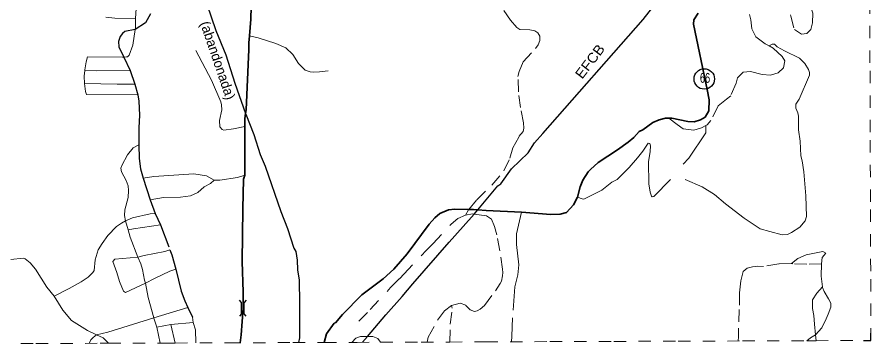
# Model space of a CAD drawing. Extents: x 423 to 448.8, y 7456.3 to 7484.
# Drawn here: x 441.81 to 448.76, y 7456.32 to 7458.99 of the extents above; entities that cross this region are included whole.
import ezdxf
from ezdxf.enums import TextEntityAlignment as Align

# ---------------------------------------------------------------- set-up
doc = ezdxf.new("R2010")
doc.units = 0
doc.header["$LTSCALE"] = 0.032
for name, pattern in [('LONG_DASHED', [7.5, 6, -1.5]), ('MEDIUM_DASHED', [4.5, 3, -1.5]), ('SHORT_DASHED', [2.7, 1.5, -1.2])]:
    doc.linetypes.add(name, pattern=pattern)
for name, color, linetype, lineweight in [('10', 7, 'Continuous', 25), ('13', 7, 'Continuous', 25), ('15', 7, 'Continuous', 25), ('2', 7, 'Continuous', 35), ('35', 7, 'SHORT_DASHED', 13), ('4', 7, 'LONG_DASHED', 25), ('5', 7, 'LONG_DASHED', 13), ('6', 7, 'MEDIUM_DASHED', 13), ('63', 7, 'Continuous', 25), ('7', 7, 'Continuous', 13), ('8', 7, 'Continuous', 13)]:
    doc.layers.add(name, color=color, linetype=linetype, lineweight=lineweight)
doc.layers.add('61', color=7, linetype='Continuous')

msp = doc.modelspace()

# ---------------------------------------------------------------- linework, layer by layer
at = {"layer": '10'}
for p, q in [((443.6717, 7456.6866), (443.6541, 7456.6689)), ((443.6541, 7456.5764), (443.6541, 7456.6689)), ((443.6341, 7456.5764), (443.6164, 7456.5589)), ((443.6717, 7456.5589), (443.6541, 7456.5764))]:
    msp.add_line(p, q, dxfattribs=at)
msp.add_lwpolyline([(443.6341, 7456.5764), (443.6341, 7456.6689), (443.6164, 7456.6866)], dxfattribs=at)
at = {"layer": '13'}
msp.add_circle((447.4, 7458.4877), 0.083, dxfattribs=at)
at = {"layer": '15'}
for points in [[(443.3513, 7459.0974), (443.4241, 7458.8825), (443.5051, 7458.6834), (443.5777, 7458.4542), (443.6658, 7458.2062), (443.6676, 7458.201), (443.7325, 7458.0356), (443.7861, 7457.8731), (443.8264, 7457.7786), (443.9522, 7457.4101), (444.006, 7457.2709), (444.0598, 7457.1111), (444.0747, 7457.0842), (444.0852, 7457.0138), (444.0887, 7456.9355), (444.1021, 7456.8492), (444.1051, 7456.6624), (444.1054, 7456.3823), (444.0975, 7456.343)], [(444.6178, 7456.3449), (444.6585, 7456.393), (444.8065, 7456.5679), (444.942, 7456.718), (445.0279, 7456.8202), (445.3242, 7457.1594), (445.5054, 7457.3621), (445.5266, 7457.3874), (445.5558, 7457.4222), (445.7199, 7457.618), (445.7438, 7457.635), (445.8297, 7457.7551), (445.9656, 7457.8865), (446.0189, 7457.9668), (446.0851, 7458.0441), (446.9025, 7458.9717), (447.0309, 7459.1371)]]:
    msp.add_lwpolyline(points, dxfattribs=at)
at = {"layer": '2'}
for points in [[(443.7131, 7459.1759), (443.7079, 7458.9733), (443.699, 7458.8387), (443.6921, 7458.7807), (443.6932, 7458.726), (443.6701, 7458.2355), (443.6658, 7458.2062), (443.6597, 7458.1653), (443.6588, 7458.1), (443.6587, 7457.7057), (443.6498, 7457.6729), (443.6426, 7457.4308), (443.6391, 7457.0014), (443.6468, 7456.7523), (443.6451, 7456.6235), (443.6304, 7456.4063), (443.6214, 7456.3412)], [(444.3062, 7456.3437), (444.3242, 7456.4136), (444.3884, 7456.5016), (444.3975, 7456.5041), (444.4559, 7456.572), (444.6115, 7456.7306), (444.7874, 7456.8606), (444.8716, 7456.9413), (444.9824, 7457.0658), (445.161, 7457.3054), (445.2065, 7457.3569), (445.2486, 7457.3922), (445.3173, 7457.424), (445.3689, 7457.4291), (445.4822, 7457.4262), (445.521, 7457.4252), (445.5558, 7457.4222), (445.6252, 7457.4163), (445.9125, 7457.4041), (446.1521, 7457.3836), (446.2277, 7457.3887), (446.2792, 7457.4024), (446.3359, 7457.4643), (446.3677, 7457.527), (446.3909, 7457.6095), (446.4123, 7457.6644), (446.4554, 7457.7323), (446.475, 7457.7512), (446.536, 7457.8087), (446.6932, 7457.9101), (446.7799, 7457.9745), (446.8255, 7458.0122), (446.8696, 7458.0602), (446.8993, 7458.075), (446.9818, 7458.1334), (447.0333, 7458.1548), (447.0848, 7458.1677), (447.1128, 7458.1677), (447.1364, 7458.1677), (447.2669, 7458.1402), (447.3184, 7458.1376), (447.3682, 7458.154), (447.406, 7458.1763), (447.4378, 7458.2287), (447.4395, 7458.3189), (447.424, 7458.4021), (447.3113, 7458.9338), (447.3158, 7458.9691), (447.3495, 7459.0218)]]:
    msp.add_lwpolyline(points, dxfattribs=at)
at = {"layer": '35'}
for points in [[(448.7566, 7456.3595), (448.7547, 7456.9244), (448.7528, 7457.4892), (448.7508, 7458.054), (448.7489, 7458.6188), (448.747, 7459.1836), (448.7451, 7459.7485), (448.7442, 7460.0136)], [(439.1532, 7456.3237), (439.3443, 7456.3245), (439.8673, 7456.3266), (440.3902, 7456.3287), (440.9131, 7456.3308), (441.436, 7456.3328), (441.9589, 7456.3348), (442.4818, 7456.3368), (442.5495, 7456.3371)], [(442.5495, 7456.3371), (443.0047, 7456.3388), (443.0935, 7456.3391)], [(443.0935, 7456.3391), (443.5276, 7456.3408), (444.0505, 7456.3428), (444.3062, 7456.3437), (444.5306, 7456.3445)], [(444.5306, 7456.3445), (444.5734, 7456.3447), (444.7656, 7456.3454)], [(444.7656, 7456.3454), (445.0963, 7456.3466), (445.3291, 7456.3474)], [(445.3291, 7456.3474), (445.6192, 7456.3485), (446.1421, 7456.3504), (446.665, 7456.3523), (447.1879, 7456.3541), (447.7108, 7456.3559), (448.2337, 7456.3578), (448.235, 7456.3578), (448.3097, 7456.358), (448.7566, 7456.3595)]]:
    msp.add_lwpolyline(points, dxfattribs=at)
at = {"layer": '4'}
msp.add_lwpolyline([(442.8916, 7459.017), (442.8511, 7458.9445), (442.7682, 7458.8895), (442.7681, 7458.8895), (442.6838, 7458.8736), (442.663, 7458.8563), (442.644, 7458.8331), (442.6324, 7458.7926), (442.6332, 7458.7488), (442.6738, 7458.6656), (442.7275, 7458.5558), (442.7652, 7458.4465), (442.789, 7458.3591), (442.7969, 7458.3075), (442.8012, 7458.1921), (442.7983, 7458.0887), (442.7984, 7457.9523), (442.8, 7457.8396), (442.8095, 7457.7572), (442.8326, 7457.6808), (442.8905, 7457.5046), (442.9311, 7457.394), (442.9724, 7457.3), (443.0493, 7457.0968), (443.0654, 7457.0572), (443.0996, 7456.9397), (443.1427, 7456.7609), (443.171, 7456.6836), (443.1968, 7456.6289), (443.2342, 7456.5498)], dxfattribs=at)
at = {"layer": '5'}
for points in [[(445.9125, 7457.4041), (445.8724, 7457.2274), (445.8724, 7457.1414), (445.8903, 7456.9764), (445.8813, 7456.8944), (445.8571, 7456.7976), (445.8387, 7456.5442), (445.8326, 7456.3938), (445.83, 7456.3493)], [(442.688, 7457.3346), (442.6566, 7457.3132), (442.6158, 7457.2862), (442.5441, 7457.2135), (442.4977, 7457.15), (442.4654, 7457.0979), (442.4419, 7457.0169), (442.4324, 7456.9301), (442.4213, 7456.9121), (442.3852, 7456.876), (442.3268, 7456.8374), (442.2306, 7456.7815), (442.1082, 7456.7211)], [(442.1082, 7456.7211), (442.0485, 7456.7949), (441.9549, 7456.9396), (441.912, 7456.9911), (441.8716, 7457.0246), (441.8545, 7457.0289), (441.7549, 7457.0194)], [(442.1082, 7456.7211), (442.1781, 7456.6062), (442.249, 7456.5214), (442.38, 7456.4415), (442.4528, 7456.406), (442.4241, 7456.3837), (442.4066, 7456.366), (442.393, 7456.3365)]]:
    msp.add_lwpolyline(points, dxfattribs=at)
at = {"layer": '6'}
msp.add_line((448.3097, 7456.358), (448.3052, 7456.4047), dxfattribs=at)
for points in [[(448.0798, 7459.2093), (448.1042, 7458.9991), (448.134, 7458.8893), (448.1908, 7458.8513), (448.2341, 7458.8567), (448.2666, 7458.8893), (448.2802, 7458.9435), (448.2829, 7459.0222), (448.2508, 7459.1283), (448.2532, 7459.1738), (448.2693, 7459.2582), (448.2639, 7459.284), (448.1862, 7459.3563), (448.1515, 7459.391), (448.1123, 7459.4679)], [(445.4562, 7457.38), (445.4797, 7457.4232), (445.4822, 7457.4262), (445.5483, 7457.5046), (445.6706, 7457.6242), (445.7684, 7457.7394), (445.8163, 7457.8428), (445.8408, 7457.9276), (445.8917, 7458.0183), (445.925, 7458.059), (445.9299, 7458.0874), (445.9279, 7458.1305), (445.9031, 7458.2544), (445.8867, 7458.3824), (445.8833, 7458.5078), (445.8927, 7458.549), (445.9254, 7458.6272), (446.025, 7458.735), (446.0475, 7458.7645), (446.0625, 7458.7993), (446.0607, 7458.8362), (446.0446, 7458.8642), (446.0196, 7458.8779), (445.9797, 7458.8868), (445.8984, 7458.8912), (445.8738, 7458.9055), (445.8215, 7458.9664), (445.7673, 7459.0446)], [(447.7671, 7459.0126), (447.7787, 7458.9694), (447.7866, 7458.8943), (447.8199, 7458.8295), (447.8957, 7458.7738), (447.9282, 7458.7562), (447.9607, 7458.7385), (448.0337, 7458.6707), (448.0552, 7458.6357), (448.0441, 7458.5776), (448.0003, 7458.5376), (447.939, 7458.5188), (447.8715, 7458.5248), (447.7754, 7458.5486), (447.717, 7458.5418), (447.671, 7458.4957), (447.6602, 7458.4523), (447.6153, 7458.3508), (447.5814, 7458.3243), (447.514, 7458.2692), (447.4544, 7458.1498), (447.4229, 7458.1134), (447.4132, 7458.1083), (447.3786, 7458.0901), (447.3142, 7458.0716), (447.2282, 7458.0826), (447.1783, 7458.1173), (447.1128, 7458.1677)], [(444.588, 7456.5163), (444.681, 7456.6132), (444.847, 7456.7905), (444.9182, 7456.8623), (444.9564, 7456.9032), (445.137, 7457.0927), (445.1924, 7457.1498), (445.339, 7457.3051), (445.3946, 7457.3526), (445.4562, 7457.38)], [(445.3432, 7456.6445), (445.412, 7456.6638), (445.4588, 7456.6472), (445.4582, 7456.6432), (445.4951, 7456.6089), (445.5286, 7456.5969), (445.5509, 7456.6003), (445.5767, 7456.6149), (445.6119, 7456.645), (445.7005, 7456.7645), (445.7396, 7456.8231), (445.7487, 7456.8414), (445.7588, 7456.8846), (445.7591, 7456.9142), (445.7563, 7456.9393), (445.7365, 7457.0902), (445.7111, 7457.2194), (445.6923, 7457.287), (445.6689, 7457.3459), (445.6261, 7457.3734), (445.5266, 7457.3874), (445.5123, 7457.3894), (445.4562, 7457.38)], [(448.3548, 7456.9829), (448.2338, 7456.9802), (448.1221, 7456.9837), (448.1099, 7456.9849), (448.007, 7456.9837), (447.8826, 7456.9621), (447.8349, 7456.9645), (447.7918, 7456.9598), (447.7499, 7456.9476), (447.7162, 7456.9208), (447.6988, 7456.8462), (447.686, 7456.748), (447.6852, 7456.6115), (447.6774, 7456.4594), (447.6791, 7456.3882), (447.6762, 7456.3558)], [(448.3052, 7456.4047), (448.2967, 7456.4929), (448.2918, 7456.5635), (448.281, 7456.6192), (448.2799, 7456.6905), (448.3176, 7456.7437), (448.3626, 7456.7956)], [(445.1434, 7456.3468), (445.1524, 7456.3864), (445.2275, 7456.5244), (445.2859, 7456.5999), (445.3432, 7456.6445)], [(445.3291, 7456.3474), (445.3321, 7456.4914), (445.3486, 7456.6225), (445.3432, 7456.6445)], [(444.5306, 7456.3445), (444.5635, 7456.3798), (444.602, 7456.393), (444.6585, 7456.393), (444.702, 7456.393), (444.7422, 7456.3749), (444.7656, 7456.3454)], [(448.235, 7456.3578), (448.2638, 7456.3821), (448.3052, 7456.4047)]]:
    msp.add_lwpolyline(points, dxfattribs=at)
at = {"layer": '63'}
msp.add_lwpolyline([(448.695, 7456.3595), (448.7566, 7456.3595), (448.7566, 7456.4202)], dxfattribs=at)
at = {"layer": '7'}
for points in [[(448.144, 7458.2511), (448.1465, 7458.2817), (448.172, 7458.324), (448.2571, 7458.5192), (448.2571, 7458.5398), (448.2483, 7458.5633), (448.2199, 7458.6128), (448.174, 7458.6579), (448.0537, 7458.7153), (447.9929, 7458.7498), (447.9706, 7458.7701), (447.9518, 7458.7701), (447.9282, 7458.7562)], [(447.9328, 7457.2459), (448.0349, 7457.2201), (448.0769, 7457.223), (448.1112, 7457.2377), (448.179, 7457.2822), (448.2211, 7457.3329), (448.2322, 7457.3698), (448.2271, 7457.5364), (448.2099, 7457.7314), (448.197, 7457.8207), (448.1867, 7457.8611), (448.1799, 7457.9822), (448.1672, 7458.0731), (448.1662, 7458.1862), (448.1622, 7458.2122), (448.144, 7458.2511)], [(447.227, 7457.7952), (447.2751, 7457.8434), (447.4132, 7458.0489), (447.4132, 7458.1083)], [(446.3677, 7457.527), (446.405, 7457.5114), (446.4189, 7457.5108), (446.5665, 7457.5819), (446.6488, 7457.6474), (446.6914, 7457.6701), (446.7894, 7457.7683), (446.8555, 7457.8448), (446.9002, 7457.9006), (446.9422, 7457.965)], [(446.9422, 7457.965), (446.9557, 7457.9614), (446.9635, 7457.9443), (446.9604, 7457.8975), (446.9457, 7457.8147), (446.9485, 7457.6334), (446.9594, 7457.5665), (446.9715, 7457.533), (446.9752, 7457.5276), (446.9903, 7457.5304), (447.1252, 7457.6687)], [(447.2436, 7457.6704), (447.3837, 7457.6112), (447.4842, 7457.5476), (447.5735, 7457.4712), (447.7238, 7457.3561), (447.8561, 7457.2685), (447.9328, 7457.2459)], [(448.3052, 7456.4047), (448.3574, 7456.4633), (448.3926, 7456.5362), (448.4094, 7456.573), (448.4315, 7456.6316), (448.4302, 7456.6623), (448.4118, 7456.6977), (448.3759, 7456.7583), (448.3631, 7456.7913), (448.3626, 7456.7956), (448.3521, 7456.8824), (448.3548, 7456.9829), (448.3603, 7457.0343), (448.3908, 7457.0711), (448.3664, 7457.0829), (448.2291, 7457.0562), (448.1616, 7457.028), (448.1099, 7456.9849)]]:
    msp.add_lwpolyline(points, dxfattribs=at)
at = {"layer": '8'}
for p, q in [((443.2342, 7456.5498), (443.2407, 7456.5066)), ((442.9437, 7456.4678), (442.9706, 7456.3387)), ((443.2407, 7456.5066), (443.0566, 7456.4901)), ((443.0566, 7456.4901), (443.0935, 7456.3391))]:
    msp.add_line(p, q, dxfattribs=at)
for points in [[(442.7745, 7459.0619), (442.7724, 7459.0214), (442.7707, 7458.9793)], [(442.7707, 7458.9793), (442.7691, 7458.8954), (442.7682, 7458.8895), (442.7477, 7458.762), (442.7191, 7458.6806), (442.7045, 7458.6686), (442.6971, 7458.667), (442.6738, 7458.6656), (442.6647, 7458.6651), (442.3798, 7458.6684), (442.3679, 7458.6275), (442.3584, 7458.5606), (442.3576, 7458.5552)], [(442.7707, 7458.9793), (442.6012, 7458.9833), (442.5288, 7458.9893)], [(443.699, 7458.8387), (443.7696, 7458.821), (443.9123, 7458.7749), (443.9938, 7458.7397), (444.052, 7458.6856), (444.0969, 7458.6143), (444.151, 7458.5602), (444.1923, 7458.5464), (444.2163, 7458.5439), (444.2678, 7458.5447), (444.339, 7458.5536)], [(443.2612, 7458.7189), (443.3892, 7458.4769), (443.4639, 7458.3017), (443.4699, 7458.2777), (443.4717, 7458.2373), (443.4545, 7458.1505), (443.4571, 7458.099), (443.476, 7458.0775), (443.4889, 7458.0715), (443.567, 7458.0809), (443.6588, 7458.1)], [(442.3576, 7458.5552), (442.3514, 7458.5113), (442.3551, 7458.4495), (442.3639, 7458.3861), (442.3718, 7458.3612), (442.789, 7458.3591)], [(442.7275, 7458.5558), (442.4522, 7458.555), (442.3576, 7458.5552)], [(442.7652, 7458.4465), (442.6206, 7458.446), (442.3551, 7458.4495)], [(442.7984, 7457.9523), (442.7502, 7457.9262), (442.7054, 7457.8704), (442.6575, 7457.783), (442.6506, 7457.7606), (442.6566, 7457.7323), (442.6951, 7457.6604), (442.709, 7457.6181), (442.7142, 7457.5803), (442.709, 7457.5236), (442.6832, 7457.424), (442.6798, 7457.3759), (442.688, 7457.3346)], [(443.411, 7457.6643), (443.3486, 7457.6986), (443.2458, 7457.7168), (442.9194, 7457.6945), (442.8326, 7457.6808)], [(443.6587, 7457.7057), (443.6004, 7457.6865), (443.4553, 7457.6643), (443.411, 7457.6643)], [(442.8905, 7457.5046), (442.9985, 7457.5236), (443.1359, 7457.527), (443.2183, 7457.5356), (443.2776, 7457.5648), (443.3283, 7457.6086), (443.3796, 7457.6383), (443.411, 7457.6643)], [(442.688, 7457.3346), (442.7454, 7457.3587), (442.8902, 7457.3913), (442.9311, 7457.394)], [(442.7898, 7457.0369), (442.7272, 7457.2011), (442.7102, 7457.2588), (442.688, 7457.3346)], [(442.9724, 7457.3), (442.7546, 7457.2685), (442.7102, 7457.2588)], [(443.0493, 7457.0968), (443.0093, 7457.0848), (442.8396, 7457.0506), (442.7898, 7457.0369)], [(442.7898, 7457.0369), (442.6013, 7457.0223), (442.5853, 7457.0013), (442.6177, 7456.9142), (442.6396, 7456.839), (442.6724, 7456.7618), (442.6894, 7456.7498), (442.8521, 7456.8253)], [(442.8521, 7456.8253), (442.8432, 7456.8503), (442.8256, 7456.9375), (442.8122, 7456.9846), (442.7898, 7457.0369)], [(443.0996, 7456.9397), (443.0486, 7456.9234), (442.9237, 7456.8628), (442.8521, 7456.8253)], [(442.8521, 7456.8253), (442.872, 7456.7084), (442.9199, 7456.5431)], [(442.5495, 7456.3371), (442.507, 7456.3814), (442.4528, 7456.406), (442.5444, 7456.4268), (442.9199, 7456.5431), (443.1968, 7456.6289)], [(442.9199, 7456.5431), (442.9203, 7456.5416), (442.9437, 7456.4678), (443.0566, 7456.4901)], [(443.2407, 7456.5066), (443.2575, 7456.4468), (443.2617, 7456.3398)]]:
    msp.add_lwpolyline(points, dxfattribs=at)

# ---------------------------------------------------------------- texts
at = {"layer": '61'}
msp.add_text('(abandonada)', height=0.08, rotation=288.742, dxfattribs=at).set_placement((443.4021, 7458.6262), align=Align.CENTER)
at = {"layer": '61', "width": 1.1}
msp.add_text('EFCB', height=0.08, rotation=52.776, dxfattribs=at).set_placement((446.501, 7458.6061), align=Align.CENTER)
at = {"layer": '61', "width": 0.7}
msp.add_text('66', height=0.08, dxfattribs=at).set_placement((447.4063, 7458.4565), align=Align.CENTER)

doc.saveas('drawing.dxf')
